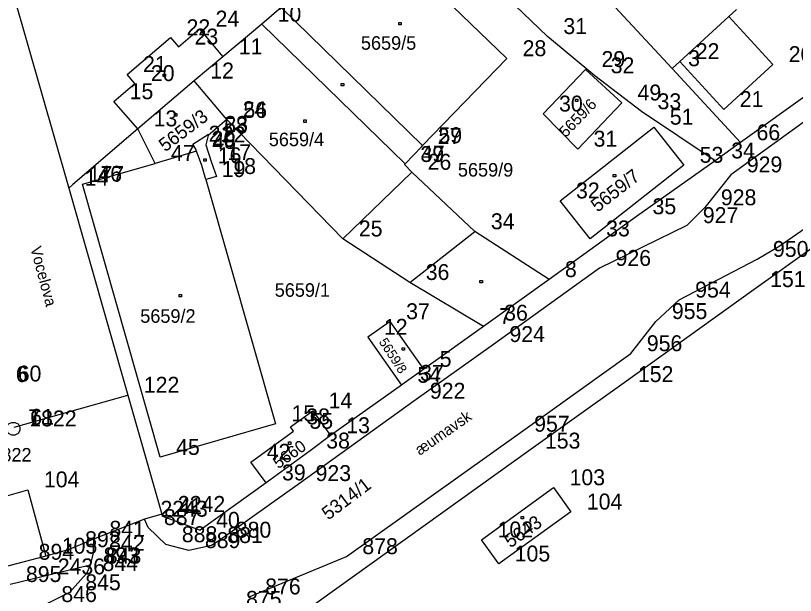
# Model space of a CAD drawing. Extents: x -822293 to -820259, y -1071573 to -1068794.
# Drawn here: x -821686.1 to -821588.1, y -1070122.7 to -1070049.8 of the extents above; entities that cross this region are included whole.
import ezdxf

# ---------------------------------------------------------------- set-up
doc = ezdxf.new("R2010")
doc.units = 0
for name, color, linetype in [('Vrstva 11', 7, 'Continuous'), ('Vrstva 14', 7, 'Continuous'), ('Vrstva 15', 7, 'Continuous'), ('Vrstva 16', 7, 'Continuous'), ('Vrstva 2', 7, 'Continuous'), ('Vrstva 3', 7, 'Continuous'), ('Vrstva 5', 7, 'Continuous'), ('Vrstva 6', 7, 'Continuous'), ('Vrstva 8', 7, 'Continuous'), ('Vrstva 9', 7, 'Continuous')]:
    doc.layers.add(name, color=color, linetype=linetype)

# ---------------------------------------------------------------- blocks, each defined once
blk = doc.blocks.new('Z402')
at = {"layer": 'Vrstva 2'}
for p, q in [((-10, 10), (20, 10)), ((-10, -20), (-10, 10)), ((20, 10), (20, -20)), ((20, -20), (-10, -20))]:
    blk.add_line(p, q, dxfattribs=at)
blk = doc.blocks.new('Z101')
at = {"layer": 'Vrstva 2'}
for p, q in [((-80, 20), (-60, 60)), ((-80, -20), (-80, 20)), ((-60, 60), (-20, 80)), ((-20, 80), (20, 80)), ((0, 0), (0, 0)), ((20, 80), (60, 60)), ((60, 60), (80, 20)), ((80, 20), (80, -20)), ((-60, -60), (-80, -20)), ((-20, -80), (-60, -60)), ((20, -80), (-20, -80)), ((60, -60), (20, -80)), ((80, -20), (60, -60))]:
    blk.add_line(p, q, dxfattribs=at)

msp = doc.modelspace()

# ---------------------------------------------------------------- linework, layer by layer
at = {"layer": 'Vrstva 2'}
for p, q in [((-821693.47, -1070022.46), (-821679.43, -1070071.53)), ((-821619.25, -1070052.46), (-821633.14, -1070039.1)), ((-821624.37, -1070055.24), (-821637.1, -1070042.94)), ((-821603.57, -1070056.5), (-821612, -1070047.38)), ((-821652.73, -1070048.83), (-821655.17, -1070050.9)), ((-821596.46, -1070049.95), (-821595.5, -1070049.07)), ((-821590.92, -1070055.98), (-821596.46, -1070049.95)), ((-821655.17, -1070050.9), (-821660.05, -1070055.01)), ((-821637.15, -1070068.47), (-821655.17, -1070050.9)), ((-821613.3, -1070057.39), (-821619.25, -1070052.46)), ((-821660.05, -1070055.01), (-821663.64, -1070058.05)), ((-821634.95, -1070066.18), (-821624.37, -1070055.24)), ((-821603.57, -1070056.5), (-821602.61, -1070055.61)), ((-821602.61, -1070055.61), (-821597.08, -1070061.63)), ((-821597.08, -1070061.63), (-821590.92, -1070055.98)), ((-821619.79, -1070062.2), (-821614.46, -1070056.6)), ((-821614.46, -1070056.6), (-821609.92, -1070060.81)), ((-821607.41, -1070061.91), (-821613.3, -1070057.39)), ((-821594.97, -1070065.81), (-821603.57, -1070056.5)), ((-821663.64, -1070058.05), (-821670.76, -1070064.06)), ((-821659.56, -1070062.91), (-821663.64, -1070058.05)), ((-821586, -1070059.37), (-821594.97, -1070065.81)), ((-821609.92, -1070060.81), (-821615.45, -1070066.61)), ((-821615.45, -1070066.61), (-821619.79, -1070062.2)), ((-821598.15, -1070068.09), (-821607.41, -1070061.91)), ((-821659.56, -1070062.91), (-821661.9, -1070064.93)), ((-821659.47, -1070063), (-821659.56, -1070062.91)), ((-821644.96, -1070077.9), (-821659.47, -1070063)), ((-821670.76, -1070064.06), (-821678.93, -1070071.06)), ((-821668.58, -1070068.41), (-821670.76, -1070064.06)), ((-821617.66, -1070073.12), (-821605.87, -1070063.85)), ((-821605.87, -1070063.85), (-821602.11, -1070068.64)), ((-821661.9, -1070064.93), (-821662.18, -1070066.07)), ((-821662.18, -1070066.07), (-821661.47, -1070068.3)), ((-821635.05, -1070066.28), (-821634.95, -1070066.18)), ((-821594.97, -1070065.81), (-821598.15, -1070068.09)), ((-821663.37, -1070066.9), (-821668.58, -1070068.41)), ((-821662.69, -1070068.7), (-821663.37, -1070066.9)), ((-821637.15, -1070068.47), (-821635.05, -1070066.28)), ((-821598.15, -1070068.09), (-821608.04, -1070075.11)), ((-821677.7, -1070071.01), (-821668.58, -1070068.41)), ((-821662.19, -1070070.43), (-821662.69, -1070068.7)), ((-821661.47, -1070068.3), (-821660.86, -1070070.05)), ((-821637.22, -1070068.54), (-821637.15, -1070068.47)), ((-821636.31, -1070069.52), (-821637.22, -1070068.54)), ((-821602.11, -1070068.64), (-821613.87, -1070077.89)), ((-821660.86, -1070070.05), (-821662.19, -1070070.43)), ((-821628.36, -1070076.99), (-821636.31, -1070069.52)), ((-821678.93, -1070071.06), (-821679.43, -1070071.53)), ((-821667.93, -1070105.36), (-821677.7, -1070071.01)), ((-821662.19, -1070070.43), (-821653.42, -1070101.13)), ((-821679.43, -1070071.53), (-821671.99, -1070097.54)), ((-821613.87, -1070077.89), (-821617.66, -1070073.12)), ((-821608.04, -1070075.11), (-821619.05, -1070083.01)), ((-821619.05, -1070083.01), (-821628.36, -1070076.99)), ((-821583.18, -1070077.05), (-821593.26, -1070084.26)), ((-821636.55, -1070083.37), (-821644.96, -1070077.9)), ((-821627.29, -1070088.91), (-821636.55, -1070083.37)), ((-821619.05, -1070083.01), (-821626.69, -1070088.48)), ((-821593.26, -1070084.26), (-821609.88, -1070096.2)), ((-821639.01, -1070088.3), (-821641.81, -1070090.26)), ((-821634.79, -1070094.28), (-821639.01, -1070088.3)), ((-821626.69, -1070088.48), (-821627.29, -1070088.91)), ((-821627.29, -1070088.91), (-821634.79, -1070094.28)), ((-821641.81, -1070090.26), (-821637.6, -1070096.29)), ((-821634.79, -1070094.28), (-821637.26, -1070096.05)), ((-821637.6, -1070096.29), (-821646.54, -1070102.63)), ((-821637.26, -1070096.05), (-821637.6, -1070096.29)), ((-821609.88, -1070096.2), (-821621.57, -1070104.56)), ((-821686.27, -1070101.57), (-821671.99, -1070097.54)), ((-821671.99, -1070097.54), (-821667.71, -1070112.52)), ((-821651.57, -1070101.52), (-821648.76, -1070099.52)), ((-821648.76, -1070099.52), (-821646.54, -1070102.63)), ((-821653.42, -1070101.13), (-821667.93, -1070105.36)), ((-821651.17, -1070102.07), (-821651.57, -1070101.52)), ((-821656.54, -1070105.96), (-821651.17, -1070102.07)), ((-821646.54, -1070102.63), (-821649.06, -1070104.55)), ((-821621.57, -1070104.56), (-821659.89, -1070131.96)), ((-821649.06, -1070104.55), (-821654.62, -1070108.56)), ((-821654.62, -1070108.56), (-821656.54, -1070105.96)), ((-821654.62, -1070108.56), (-821662.9, -1070114.52)), ((-821627.52, -1070115.73), (-821618.47, -1070109.17)), ((-821618.47, -1070109.17), (-821616.3, -1070112.22)), ((-821704.68, -1070115.12), (-821684.55, -1070109.43)), ((-821684.55, -1070109.43), (-821682.3, -1070117.77)), ((-821616.3, -1070112.22), (-821625.37, -1070118.75)), ((-821669.9, -1070113.12), (-821676.31, -1070115.64)), ((-821667.71, -1070112.52), (-821669.9, -1070113.12)), ((-821667.71, -1070112.52), (-821667.64, -1070112.77)), ((-821667.64, -1070112.77), (-821662.9, -1070114.52)), ((-821676.31, -1070115.64), (-821679.37, -1070116.95)), ((-821625.37, -1070118.75), (-821627.52, -1070115.73)), ((-821679.37, -1070116.95), (-821682.3, -1070117.77)), ((-821682.3, -1070117.77), (-821685.21, -1070118.53)), ((-821685.21, -1070118.53), (-821699.46, -1070122.27))]:
    msp.add_line(p, q, dxfattribs=at)
at = {"layer": 'Vrstva 3'}
for p, q in [((-821634.95, -1070066.18), (-821652.73, -1070048.83)), ((-821602.61, -1070055.61), (-821596.46, -1070049.95)), ((-821665.61, -1070053.78), (-821662.97, -1070051.52)), ((-821662.97, -1070051.52), (-821660.05, -1070055.01)), ((-821672.09, -1070057.23), (-821666.62, -1070052.61)), ((-821666.62, -1070052.61), (-821665.61, -1070053.78)), ((-821671.1, -1070058.37), (-821672.09, -1070057.23)), ((-821673.77, -1070060.65), (-821671.1, -1070058.37)), ((-821670.76, -1070064.06), (-821673.77, -1070060.65)), ((-821585.76, -1070062.3), (-821596.19, -1070069.84)), ((-821663.84, -1070065.98), (-821661.86, -1070064.76)), ((-821661.86, -1070064.76), (-821661.9, -1070064.93)), ((-821663.47, -1070066.64), (-821663.84, -1070065.98)), ((-821663.37, -1070066.9), (-821663.47, -1070066.64)), ((-821644.96, -1070077.9), (-821636.31, -1070069.52)), ((-821596.19, -1070069.84), (-821599.45, -1070073.98)), ((-821590.11, -1070078.84), (-821578.77, -1070070.83)), ((-821599.45, -1070073.98), (-821601.72, -1070076.22)), ((-821636.55, -1070083.37), (-821628.36, -1070076.99)), ((-821601.72, -1070076.22), (-821612.69, -1070081.6)), ((-821592.9, -1070080.47), (-821590.11, -1070078.84)), ((-821602.68, -1070085.58), (-821592.9, -1070080.47)), ((-821612.69, -1070081.6), (-821626.03, -1070091.17)), ((-821605.61, -1070088.28), (-821602.68, -1070085.58)), ((-821608.76, -1070092.32), (-821605.61, -1070088.28)), ((-821626.03, -1070091.17), (-821636.03, -1070098.29)), ((-821622.92, -1070102.44), (-821608.76, -1070092.32)), ((-821636.03, -1070098.29), (-821650.4, -1070108.64)), ((-821644.52, -1070117.83), (-821622.92, -1070102.44)), ((-821650.4, -1070108.64), (-821660.43, -1070115.76)), ((-821669.46, -1070114.18), (-821669.9, -1070113.12)), ((-821667.21, -1070116.33), (-821669.46, -1070114.18)), ((-821676.31, -1070115.64), (-821676.35, -1070117.41)), ((-821660.43, -1070115.76), (-821661.49, -1070116.43)), ((-821664.31, -1070117.07), (-821667.21, -1070116.33)), ((-821661.49, -1070116.43), (-821664.31, -1070117.07)), ((-821676.35, -1070117.41), (-821676.77, -1070119.02)), ((-821656.73, -1070122.89), (-821644.52, -1070117.83)), ((-821677.05, -1070118.98), (-821682.81, -1070120.37)), ((-821676.77, -1070119.02), (-821677.18, -1070119.95)), ((-821676.77, -1070119.02), (-821677.05, -1070118.98)), ((-821677.18, -1070119.95), (-821679.35, -1070122.37)), ((-821682.81, -1070120.37), (-821686.81, -1070121.33)), ((-821679.35, -1070122.37), (-821682.35, -1070123.85))]:
    msp.add_line(p, q, dxfattribs=at)
at = {"layer": 'Vrstva 8'}
for p, q in [((-821596.46, -1070049.95), (-821596.46, -1070049.95)), ((-821662.97, -1070051.52), (-821662.97, -1070051.52)), ((-821655.17, -1070050.9), (-821655.17, -1070050.9)), ((-821619.25, -1070052.46), (-821619.25, -1070052.46)), ((-821666.62, -1070052.61), (-821666.62, -1070052.61)), ((-821665.61, -1070053.78), (-821665.61, -1070053.78)), ((-821660.05, -1070055.01), (-821660.05, -1070055.01)), ((-821624.37, -1070055.24), (-821624.37, -1070055.24)), ((-821602.61, -1070055.61), (-821602.61, -1070055.61)), ((-821590.92, -1070055.98), (-821590.92, -1070055.98)), ((-821672.09, -1070057.23), (-821672.09, -1070057.23)), ((-821614.46, -1070056.6), (-821614.46, -1070056.6)), ((-821613.3, -1070057.39), (-821613.3, -1070057.39)), ((-821603.57, -1070056.5), (-821603.57, -1070056.5)), ((-821671.1, -1070058.37), (-821671.1, -1070058.37)), ((-821663.64, -1070058.05), (-821663.64, -1070058.05)), ((-821673.77, -1070060.65), (-821673.77, -1070060.65)), ((-821609.92, -1070060.81), (-821609.92, -1070060.81)), ((-821619.79, -1070062.2), (-821619.79, -1070062.2)), ((-821607.41, -1070061.91), (-821607.41, -1070061.91)), ((-821597.08, -1070061.63), (-821597.08, -1070061.63)), ((-821659.56, -1070062.91), (-821659.56, -1070062.91)), ((-821659.47, -1070063), (-821659.47, -1070063)), ((-821670.76, -1070064.06), (-821670.76, -1070064.06)), ((-821605.87, -1070063.85), (-821605.87, -1070063.85)), ((-821661.9, -1070064.93), (-821661.9, -1070064.93)), ((-821661.86, -1070064.76), (-821661.86, -1070064.76)), ((-821663.84, -1070065.98), (-821663.84, -1070065.98)), ((-821662.18, -1070066.07), (-821662.18, -1070066.07)), ((-821634.95, -1070066.18), (-821634.95, -1070066.18)), ((-821594.97, -1070065.81), (-821594.97, -1070065.81)), ((-821663.47, -1070066.64), (-821663.47, -1070066.64)), ((-821663.37, -1070066.9), (-821663.37, -1070066.9)), ((-821635.05, -1070066.28), (-821635.05, -1070066.28)), ((-821615.45, -1070066.61), (-821615.45, -1070066.61)), ((-821598.15, -1070068.09), (-821598.15, -1070068.09)), ((-821668.58, -1070068.41), (-821668.58, -1070068.41)), ((-821662.69, -1070068.7), (-821662.69, -1070068.7)), ((-821661.47, -1070068.3), (-821661.47, -1070068.3)), ((-821637.22, -1070068.54), (-821637.22, -1070068.54)), ((-821637.15, -1070068.47), (-821637.15, -1070068.47)), ((-821602.11, -1070068.64), (-821602.11, -1070068.64)), ((-821660.86, -1070070.05), (-821660.86, -1070070.05)), ((-821636.31, -1070069.52), (-821636.31, -1070069.52)), ((-821596.19, -1070069.84), (-821596.19, -1070069.84)), ((-821678.93, -1070071.06), (-821678.93, -1070071.06)), ((-821677.7, -1070071.01), (-821677.7, -1070071.01)), ((-821662.19, -1070070.43), (-821662.19, -1070070.43)), ((-821679.43, -1070071.53), (-821679.43, -1070071.53)), ((-821617.66, -1070073.12), (-821617.66, -1070073.12)), ((-821599.45, -1070073.98), (-821599.45, -1070073.98)), ((-821608.04, -1070075.11), (-821608.04, -1070075.11)), ((-821628.36, -1070076.99), (-821628.36, -1070076.99)), ((-821601.72, -1070076.22), (-821601.72, -1070076.22)), ((-821644.96, -1070077.9), (-821644.96, -1070077.9)), ((-821613.87, -1070077.89), (-821613.87, -1070077.89)), ((-821590.11, -1070078.84), (-821590.11, -1070078.84)), ((-821592.9, -1070080.47), (-821592.9, -1070080.47)), ((-821612.69, -1070081.6), (-821612.69, -1070081.6)), ((-821636.55, -1070083.37), (-821636.55, -1070083.37)), ((-821619.05, -1070083.01), (-821619.05, -1070083.01)), ((-821593.26, -1070084.26), (-821593.26, -1070084.26)), ((-821602.68, -1070085.58), (-821602.68, -1070085.58)), ((-821639.01, -1070088.3), (-821639.01, -1070088.3)), ((-821626.69, -1070088.48), (-821626.69, -1070088.48)), ((-821605.61, -1070088.28), (-821605.61, -1070088.28)), ((-821627.29, -1070088.91), (-821627.29, -1070088.91)), ((-821641.81, -1070090.26), (-821641.81, -1070090.26)), ((-821626.03, -1070091.17), (-821626.03, -1070091.17)), ((-821608.76, -1070092.32), (-821608.76, -1070092.32)), ((-821634.79, -1070094.28), (-821634.79, -1070094.28)), ((-821637.6, -1070096.29), (-821637.6, -1070096.29)), ((-821637.26, -1070096.05), (-821637.26, -1070096.05)), ((-821609.88, -1070096.2), (-821609.88, -1070096.2)), ((-821671.99, -1070097.54), (-821671.99, -1070097.54)), ((-821636.03, -1070098.29), (-821636.03, -1070098.29)), ((-821648.76, -1070099.52), (-821648.76, -1070099.52)), ((-821653.42, -1070101.13), (-821653.42, -1070101.13)), ((-821651.57, -1070101.52), (-821651.57, -1070101.52)), ((-821651.17, -1070102.07), (-821651.17, -1070102.07)), ((-821622.92, -1070102.44), (-821622.92, -1070102.44)), ((-821646.54, -1070102.63), (-821646.54, -1070102.63)), ((-821667.93, -1070105.36), (-821667.93, -1070105.36)), ((-821649.06, -1070104.55), (-821649.06, -1070104.55)), ((-821621.57, -1070104.56), (-821621.57, -1070104.56)), ((-821656.54, -1070105.96), (-821656.54, -1070105.96)), ((-821654.62, -1070108.56), (-821654.62, -1070108.56)), ((-821650.4, -1070108.64), (-821650.4, -1070108.64)), ((-821618.47, -1070109.17), (-821618.47, -1070109.17)), ((-821684.55, -1070109.43), (-821684.55, -1070109.43)), ((-821616.3, -1070112.22), (-821616.3, -1070112.22)), ((-821669.9, -1070113.12), (-821669.9, -1070113.12)), ((-821667.71, -1070112.52), (-821667.71, -1070112.52)), ((-821667.64, -1070112.77), (-821667.64, -1070112.77)), ((-821669.46, -1070114.18), (-821669.46, -1070114.18)), ((-821662.9, -1070114.52), (-821662.9, -1070114.52)), ((-821676.31, -1070115.64), (-821676.31, -1070115.64)), ((-821660.43, -1070115.76), (-821660.43, -1070115.76)), ((-821627.52, -1070115.73), (-821627.52, -1070115.73)), ((-821679.37, -1070116.95), (-821679.37, -1070116.95)), ((-821667.21, -1070116.33), (-821667.21, -1070116.33)), ((-821664.31, -1070117.07), (-821664.31, -1070117.07)), ((-821661.49, -1070116.43), (-821661.49, -1070116.43)), ((-821682.3, -1070117.77), (-821682.3, -1070117.77)), ((-821676.35, -1070117.41), (-821676.35, -1070117.41)), ((-821644.52, -1070117.83), (-821644.52, -1070117.83)), ((-821685.21, -1070118.53), (-821685.21, -1070118.53)), ((-821677.05, -1070118.98), (-821677.05, -1070118.98)), ((-821676.77, -1070119.02), (-821676.77, -1070119.02)), ((-821625.37, -1070118.75), (-821625.37, -1070118.75)), ((-821677.18, -1070119.95), (-821677.18, -1070119.95)), ((-821682.81, -1070120.37), (-821682.81, -1070120.37)), ((-821679.35, -1070122.37), (-821679.35, -1070122.37))]:
    msp.add_line(p, q, dxfattribs=at)

# ---------------------------------------------------------------- block references
at = {"layer": 'Vrstva 11', "xscale": 0.01, "yscale": 0.01}
for p in [(-821637.84, -1070050.82), (-821667.46, -1070057.3), (-821645.06, -1070058.47), (-821615.63, -1070060.43), (-821666.02, -1070062.26), (-821649.76, -1070063.06), (-821662.35, -1070067.95), (-821610.87, -1070069.92), (-821627.63, -1070083.22), (-821665.44, -1070084.98), (-821637.42, -1070091.71), (-821651.71, -1070103.53), (-821622.45, -1070112.9)]:
    msp.add_blockref('Z402', p, dxfattribs=at)
at = {"layer": 'Vrstva 14', "xscale": 0.01, "yscale": 0.01}
msp.add_blockref('Z101', (-821686.39, -1070101.77), dxfattribs=at)

# ---------------------------------------------------------------- texts
at = {"layer": 'Vrstva 15'}
for s, rotation, p in [('Vocelova', 285, (-821684.264, -1070079.067)), ('æumavsk\xa0', 35, (-821635.292, -1070105.179))]:
    msp.add_text(s, height=1.4, rotation=rotation, dxfattribs=at).set_placement(p)
at = {"layer": 'Vrstva 16'}
msp.add_text('1822', height=1.7, dxfattribs=at).set_placement((-821689.16, -1070105.89))
at = {"layer": 'Vrstva 5'}
for s, p in [('5659/9', (-821630.506, -1070070.07)), ('5659/1', (-821653.533, -1070085.18))]:
    msp.add_text(s, height=1.7, dxfattribs=at).set_placement(p)
msp.add_text('5314/1', height=1.7, rotation=37, dxfattribs=at).set_placement((-821646.81, -1070113.318))
at = {"layer": 'Vrstva 6'}
for s, p in [('5659/5', (-821642.698, -1070054.13)), ('5659/4', (-821654.276, -1070066.25)), ('5659/2', (-821670.436, -1070088.45))]:
    msp.add_text(s, height=1.7, dxfattribs=at).set_placement(p)
for s, height, rotation, p in [('5659/6', 1.4, 46, (-821616.928, -1070065.225)), ('5659/3', 1.7, 37, (-821667.3, -1070067.04)), ('5659/7', 1.699, 38, (-821612.958, -1070074.62)), ('5659/8', 1.199, 303, (-821640.49, -1070090.85)), ('5660', 1.5, 35, (-821653.09, -1070106.866)), ('5643', 1.7, 35, (-821623.915, -1070116.817))]:
    msp.add_text(s, height=height, rotation=rotation, dxfattribs=at).set_placement(p)
at = {"layer": 'Vrstva 9'}
for s, p in [('10', (-821653.17, -1070050.6)), ('24', (-821660.97, -1070051.22)), ('22', (-821664.62, -1070052.31)), ('31', (-821617.25, -1070052.16)), ('23', (-821663.61, -1070053.48)), ('11', (-821658.05, -1070054.71)), ('28', (-821622.37, -1070054.94)), ('22', (-821600.61, -1070055.31)), ('29', (-821612.46, -1070056.3)), ('3', (-821601.57, -1070056.2)), ('20', (-821588.92, -1070055.68)), ('21', (-821670.09, -1070056.93)), ('32', (-821611.3, -1070057.09)), ('20', (-821669.1, -1070058.07)), ('12', (-821661.64, -1070057.75)), ('15', (-821671.77, -1070060.35)), ('49', (-821607.92, -1070060.51)), ('21', (-821595.08, -1070061.33)), ('30', (-821617.79, -1070061.9)), ('33', (-821605.41, -1070061.61)), ('24', (-821657.56, -1070062.61)), ('56', (-821657.47, -1070062.7)), ('13', (-821668.76, -1070063.76)), ('51', (-821603.87, -1070063.55)), ('58', (-821659.9, -1070064.63)), ('23', (-821659.86, -1070064.46)), ('21', (-821661.84, -1070065.68)), ('22', (-821660.18, -1070065.77)), ('27', (-821633.05, -1070065.98)), ('59', (-821632.95, -1070065.88)), ('31', (-821613.45, -1070066.31)), ('66', (-821592.97, -1070065.51)), ('20', (-821661.47, -1070066.34)), ('48', (-821661.37, -1070066.6)), ('47', (-821666.58, -1070068.11)), ('17', (-821659.47, -1070068)), ('39', (-821635.22, -1070068.24)), ('47', (-821635.15, -1070068.17)), ('34', (-821596.15, -1070067.79)), ('16', (-821660.69, -1070068.4)), ('26', (-821634.31, -1070069.22)), ('53', (-821600.11, -1070068.34)), ('19', (-821660.19, -1070070.13)), ('18', (-821658.86, -1070069.75)), ('929', (-821594.19, -1070069.54)), ('177', (-821676.93, -1070070.76)), ('46', (-821675.7, -1070070.71)), ('14', (-821677.43, -1070071.23)), ('32', (-821615.66, -1070072.82)), ('928', (-821597.45, -1070073.68)), ('35', (-821606.04, -1070074.81)), ('927', (-821599.72, -1070075.92)), ('34', (-821626.36, -1070076.69)), ('25', (-821642.96, -1070077.6)), ('33', (-821611.87, -1070077.59)), ('950', (-821590.9, -1070080.17)), ('926', (-821610.69, -1070081.3)), ('8', (-821617.05, -1070082.71)), ('36', (-821634.55, -1070083.07)), ('151', (-821591.26, -1070083.96)), ('954', (-821600.68, -1070085.28)), ('37', (-821637.01, -1070088)), ('7', (-821625.29, -1070088.61)), ('36', (-821624.69, -1070088.18)), ('955', (-821603.61, -1070087.98)), ('12', (-821639.81, -1070089.96)), ('924', (-821624.03, -1070090.87)), ('956', (-821606.76, -1070092.02)), ('5', (-821632.79, -1070093.98)), ('6', (-821686.08, -1070095.9)), ('60', (-821685.84, -1070095.83)), ('54', (-821635.6, -1070095.99)), ('37', (-821635.26, -1070095.75)), ('152', (-821607.88, -1070095.9)), ('122', (-821669.99, -1070097.24)), ('922', (-821634.03, -1070097.99)), ('14', (-821646.76, -1070099.22)), ('7', (-821684.51, -1070101.34)), ('1822', (-821684.39, -1070101.47)), ('61', (-821684.27, -1070101.27)), ('15', (-821651.42, -1070100.83)), ('38', (-821649.57, -1070101.22)), ('55', (-821649.17, -1070101.77)), ('13', (-821644.54, -1070102.33)), ('957', (-821620.92, -1070102.14)), ('38', (-821647.06, -1070104.25)), ('153', (-821619.57, -1070104.26)), ('45', (-821665.93, -1070105.06)), ('42', (-821654.54, -1070105.66)), ('39', (-821652.62, -1070108.26)), ('923', (-821648.4, -1070108.34)), ('104', (-821682.55, -1070109.13)), ('103', (-821616.47, -1070108.87)), ('2242', (-821665.71, -1070112.22)), ('104', (-821614.3, -1070111.92)), ('2243', (-821667.9, -1070112.82)), ('41', (-821665.64, -1070112.47)), ('887', (-821667.46, -1070113.88)), ('40', (-821660.9, -1070114.22)), ('841', (-821674.31, -1070115.34)), ('888', (-821665.21, -1070116.03)), ('881', (-821659.49, -1070116.13)), ('880', (-821658.43, -1070115.46)), ('102', (-821625.52, -1070115.43)), ('892', (-821677.37, -1070116.65)), ('842', (-821674.35, -1070117.11)), ('889', (-821662.31, -1070116.77)), ('894', (-821683.21, -1070118.23)), ('105', (-821680.3, -1070117.47)), ('878', (-821642.52, -1070117.53)), ('893', (-821675.05, -1070118.68)), ('843', (-821674.77, -1070118.72)), ('105', (-821623.37, -1070118.45)), ('2436', (-821680.81, -1070120.07)), ('844', (-821675.18, -1070119.65)), ('895', (-821684.81, -1070121.03)), ('845', (-821677.35, -1070122.07)), ('876', (-821654.73, -1070122.59)), ('846', (-821680.35, -1070123.55)), ('875', (-821657.14, -1070124.15))]:
    msp.add_text(s, height=2, dxfattribs=at).set_placement(p)

doc.saveas('drawing.dxf')
